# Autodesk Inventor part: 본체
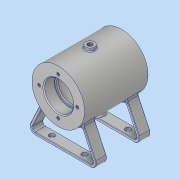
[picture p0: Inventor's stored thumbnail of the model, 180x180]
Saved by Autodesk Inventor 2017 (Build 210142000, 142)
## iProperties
Part Number: 본체
Material: 알루미늄 6061
Document SubType Name: Modeling
Designer: Administrator
Density: 2.7 g/cm^3
Appearance: 알루미늄 - 평지
Mass: 310.254 g
Surface Area: 354.969 cm^2
Volume: 114.909 cm^3
Author: Administrator
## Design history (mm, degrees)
sketch "스케치1"
  geometry: C1 r 29 at (0, 0); 1 further point
  constraints: 1 centre point, 1 coincident
  dimensions: "d0" = 58 diameter of C1
extrude "돌출1" new body sketch "스케치1" stored distance "d1" = 70; taper "d2" = 0 deg
sketch "스케치2"
  geometry: C1 r 16 at (0, 0); 1 further point
  constraints: 1 centre point, 1 coincident
  dimensions: "d3" = 32 diameter of C1
extrude "돌출2" cut sketch "스케치2" distance "d4" = 12; taper "d5" = 0 deg
sketch "스케치3"
  geometry: C1 r 14 at (0, 0); 1 further point
  constraints: 1 centre point, 1 coincident
  dimensions: "d6" = 28 diameter of C1
extrude "돌출3" cut sketch "스케치3" distance "d7" = 2; taper "d8" = 0 deg
sketch "스케치4"
  geometry: C1 r 21 at (0, 0); 1 further point
  constraints: 1 centre point, 1 coincident
  dimensions: "d9" = 42 diameter of C1
extrude "돌출4" cut sketch "스케치4" distance "d10" = 42; taper "d11" = 0 deg
sketch "스케치5" dims "d12" = 42
  geometry: 3 further points
  constraints: 2 vertical alignment, 1 coincident, 2 other
hole "구멍1" sketch "스케치5" at (0, 21) diameter "d13" = 3.242; stored, may be unused: countersink angle "d17" = 90 deg, drill point angle "d19" = 118 deg; dims "d14" = 8, "d15" = 4, "d16" = 2, "d18" = 10
node "작업 평면2"
sketch "스케치7"
  geometry: C1 r 5 at (0, 0); 1 further point
  constraints: 1 centre point, 1 coincident
  dimensions: "d28" = 10 diameter of C1
extrude "돌출6" join sketch "스케치7" stored distance "d29" = 42; taper "d30" = 0 deg
sketch "스케치8"
  geometry: 1 further point
hole "구멍2" sketch "스케치8" at (0, 0) diameter "d31" = 5.188; stored, may be unused: countersink angle "d35" = 90 deg, drill point angle "d37" = 118 deg; dims "d32" = 6, "d33" = 4, "d34" = 2, "d36" = 8
sketch "스케치9"
  geometry: C1 r 1.5 at (0, 0); 1 further point
  constraints: 1 centre point, 1 coincident
  dimensions: "d38" = 3 diameter of C1
extrude "돌출7" cut sketch "스케치9" distance "d39" = 16; taper "d40" = 0 deg
node "작업 평면3"
sketch "스케치10"
  geometry: L1 (-40, -55)-(40, -55); L2 (-35.291, -52)-(35.291, -52); L3 (-35.291, -52)-(-18.723, -16.469); L4 (-40, -55)-(-22.033, -16.469); L5 (-22.033, -16.469)-(-18.723, -16.469); L6 (35.291, -52)-(18.723, -16.469); L7 (18.723, -16.469)-(22.033, -16.469); L8 (22.033, -16.469)-(40, -55); C1 r 29 at (0, 0) reference; C2 r 1.621 at (21, 0) reference; C3 r 1.621 at (0, -21) reference; C4 r 1.621 at (-21, 0) reference; C5 r 1.621 at (0, 21) reference; C6 r 16 at (0, 0) reference; C7 r 29 at (0, 0) reference; 2 further points
  constraints: 16 end point, 3 horizontal, 3 parallel, 1 horizontal alignment, 1 midpoint, 1 vertical alignment
  dimensions: "d43" = 3 distance between parallel lines of L1 L2; "d44" = 55 distance from line of L1 point (0, 0); "d48" = 80 distance of L1.start L1.end; "d51" = 65 deg angle of L1 L8; "d52" = 65 deg angle of L1 L4; "d53" = 3 distance between parallel lines of L3 L4; "d54" = 3 distance between parallel lines of L8 L6; "d56" = 16.4693 distance from line of L5 C1.centre
extrude "돌출8" join sketch "스케치10" distance "d57" = 12; taper "d58" = 0 deg
sketch "스케치11"
  geometry: L1 (70.582, 0)-(70.582, 12) reference; L2 (0, 12)-(70.582, 12) reference; L3 (-3.31, 12)-(0, 12) reference; L4 (-3.31, 0)-(-3.31, 12) reference; L5 (0, 0)-(-3.31, 0) reference; L6 (70.582, 0)-(0, 0) reference; L7 (73.892, 0)-(70.582, 0) reference; L8 (73.892, 12)-(73.892, 0) reference; L9 (70.582, 12)-(73.892, 12) reference; L10 (0, 12)-(0, 0) reference; L11 (-4.709, 0)-(-4.709, 12) reference; C1 r 3 at (17.291, 6); C2 r 3 at (53.291, 6); 1 further point
  constraints: 2 centre point, 1 horizontal alignment
  dimensions: "d59" = 6 diameter of C1; "d60" = 6 diameter of C2; "d61" = 6 distance from line of C1.centre L2; "d62" = 36 distance of C2.centre C1.centre; "d63" = 22 distance from line of C1.centre L11
extrude "돌출9" cut sketch "스케치11" stored distance "d64" = 12; taper "d65" = 0 deg
node "작업 평면5"
  node "작업 평면4"
sketch "스케치12"
  geometry: C1 r 6 at (0, 0); 1 further point
  constraints: 1 centre point, 1 coincident
  dimensions: "d68" = 12 diameter of C1
extrude "돌출10" join sketch "스케치12" stored distance "d69" = 12; taper "d70" = 0 deg
sketch "스케치13"
  geometry: 1 further point
hole "구멍3" sketch "스케치13" at (0, 0) diameter "d71" = 5.188; stored, may be unused: countersink angle "d75" = 90 deg, drill point angle "d77" = 118 deg; dims "d72" = 25, "d73" = 4, "d74" = 2, "d76" = 29.5
fillet "모깎기1" dims "d78" = 6
fillet "모깎기3" dims "d80" = 1
chamfer "모따기1" distance "d82" = 1; stored, may be unused: second distance "d83" = 2, angle "d84" = 45 deg
fillet "모깎기5" dims "d85" = 3, "d86" = 0.3
node "작업 평면6"
sketch "스케치14"
  geometry: L1 (-29, -35)-(29, -35) reference; L2 (-29, -35)-(-29, 35) reference; 2 further points
  constraints: 1 other
  dimensions: "d87" = 35 distance from line of point (0, 0) L1; "d88" = 29 distance from line of point (0, 0) L2
feature "엠보싱1" sketch "스케치14" dims "d89" = 0.5, "d90" = 0
fillet "모깎기8" dims "d93" = 3
fillet "모깎기9" dims "d94" = 0.5
fillet "모깎기10" dims "d95" = 3
node "솔리드1"
pattern_circular "원형 패턴1" dims angle "d21" = 360 deg
mirror "미러1"
mirror "미러2"
node "절단 모서리 투영1"
node "절단 모서리 투영2"
other parameters: "d27" = 32, "d41" = -5, "d66" = 110 deg, "d67" = -32
